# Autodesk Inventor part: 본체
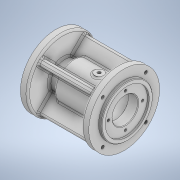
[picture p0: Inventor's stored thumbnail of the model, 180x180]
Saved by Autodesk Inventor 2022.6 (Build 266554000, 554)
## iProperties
Created: 2024-10
Part Number: 본체
Material: 일반
Document SubType Name: Modeling
Designer: Class 001
Density: 1 g/cm^3
Appearance: 기본값
Author: Class 001
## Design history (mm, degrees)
sketch "스케치3"
  geometry: L1 (0, 0)-(15, 0); L2 (15, 0)-(15, 23); L3 (15, 23)-(0, 23); L4 (0, 23)-(0, 0); L5 (15, 0)-(88, 0); L6 (88, 0)-(88, 30); L7 (88, 30)-(15, 30); L8 (15, 30)-(15, 0); 1 further point
  constraints: 16 end point, 4 parallel, 2 horizontal, 2 perpendicular
  dimensions: "d7" = 46 diameter of L3 L1; "d8" = 15 distance of L2.end L3.end; "d9" = 73 distance of L6.end L7.end; "d10" = 60 diameter of L7 L5
revolve "회전1" sketch "스케치3" stored, may be unused: angle "d11" = 90 deg
sketch "스케치4"
  geometry: C1 r 58 at (0, 0); 1 further point
  constraints: 1 centre point, 1 coincident
  dimensions: "d12" = 116 diameter of C1
extrude "돌출1" join sketch "스케치4" distance "d13" = 12; taper "d14" = 0 deg
sketch "스케치5"
  geometry: C1 r 42 at (0, 0); 1 further point
  constraints: 1 centre point, 1 coincident
  dimensions: "d15" = 84 diameter of C1
extrude "돌출2" join sketch "스케치5" distance "d16" = 5; taper "d17" = 0 deg
sketch "스케치6"
  geometry: C1 r 58 at (0, 0); 1 further point
  constraints: 1 centre point, 1 coincident
  dimensions: "d18" = 116 diameter of C1
extrude "돌출3" join sketch "스케치6" distance "d19" = 12; taper "d20" = 0 deg
sketch "스케치7"
  geometry: C1 r 42 at (0, 0); 1 further point
  constraints: 1 centre point, 1 coincident
  dimensions: "d21" = 84 diameter of C1
extrude "돌출4" join sketch "스케치7" distance "d22" = 5; taper "d23" = 0 deg
sketch "스케치8"
  geometry: L1 (105, -42)-(105, 42) reference; L2 (105, 36)-(102, 36); L3 (102, 36)-(102, 0); L4 (102, 0)-(105, 0); L5 (105, 0)-(105, 36); L6 (102, 0)-(86, 0); L7 (86, 0)-(86, 21); L8 (86, 21)-(102, 21); L9 (102, 21)-(102, 0); L10 (86, 0)-(32, 0); L11 (32, 0)-(32, 25); L12 (32, 25)-(86, 25); L13 (86, 25)-(86, 0); L14 (32, 0)-(20, 0); L15 (20, 0)-(20, 21); L16 (20, 21)-(32, 21); L17 (32, 21)-(32, 0); L18 (20, 0)-(2, 0); L19 (2, 0)-(2, 18); L20 (2, 18)-(20, 18); L21 (20, 18)-(20, 0); L22 (2, 0)-(-2, 0); L23 (-2, 0)-(-2, 16); L24 (-2, 16)-(2, 16); L25 (2, 16)-(2, 0); L26 (-2, 0)-(-5, 0); L27 (-5, 0)-(-5, 10.5); L28 (-5, 10.5)-(-2, 10.5); L29 (-2, 10.5)-(-2, 0); 8 further points
  constraints: 56 end point, 14 parallel, 7 horizontal, 7 perpendicular, 1 horizontal alignment, 1 point on line
  dimensions: "d24" = 72 diameter of L2 L4; "d25" = 3 distance of L2.start L2.end; "d26" = 42 diameter of L8 L6; "d27" = 16 distance of L7.end L8.end; "d28" = 54 distance of L11.end L12.end; "d29" = 50 diameter of L12 L10; "d30" = 12 distance of L15.end L16.end; "d31" = 42 diameter of L16 L14; "d32" = 18 distance of L19.end L20.end; "d33" = 36 diameter of L20 L18; "d34" = 4 distance of L23.end L24.end; "d35" = 32 diameter of L24 L22; "d36" = 3 distance of L27.end L28.end; "d37" = 21 diameter of L28 L26
revolve "회전2" stored, may be unused: angle "d38" = 90 deg
revolve "회전3" stored, may be unused: angle "d39" = 90 deg
fillet "모깎기1" dims "d40" = 3
fillet "모깎기2" dims "d41" = 0.6
chamfer "모따기1" distance "d42" = 1; stored, may be unused: second distance "d43" = 2, angle "d44" = 30 deg
fillet "모깎기3" dims "d45" = 0.6
fillet "모깎기4" dims "d46" = 3
chamfer "모따기2" distance "d47" = 1; stored, may be unused: second distance "d48" = 2, angle "d49" = 30 deg
chamfer "모따기3" distance "d50" = 1; stored, may be unused: second distance "d51" = 2, angle "d52" = 30 deg
sketch "스케치9"
  geometry: C1 r 36 at (0, 0); 1 further point
  constraints: 1 centre point, 1 coincident
  dimensions: "d53" = 72 diameter of C1
extrude "돌출5" cut sketch "스케치9" distance "d54" = 4; taper "d55" = 0 deg
fillet "모깎기5" dims "d56" = 3
fillet "모깎기6" dims "d57" = 3
sketch "스케치10"
  geometry: 2 further points
  constraints: 1 horizontal alignment
  dimensions: "d58" = 28 distance of point (0, 0) point (28, 0)
hole "구멍1" sketch "스케치10" at (28, 0) diameter "d59" = 4.134; stored, may be unused: countersink angle "d63" = 82 deg, drill point angle "d65" = 118 deg; dims "d60" = 10, "d61" = 11, "d62" = 2.6, "d64" = 12
node "작업 평면4"
sketch "스케치12"
  geometry: L1 (-105, -41)-(-105, 41) reference; C1 r 7.5 at (-59, 0); 2 further points
  constraints: 1 centre point, 1 horizontal alignment, 1 midpoint
  dimensions: "d74" = 15 diameter of C1; "d75" = 46 distance from line of L1 C1.centre
extrude "돌출6" join sketch "스케치12" stored distance "d76" = 4; taper "d77" = 0 deg
sketch "스케치13"
  geometry: C1 r 7.5 at (0, 0) reference; 2 further points
  constraints: 1 coincident
hole "구멍2" sketch "스케치13" at (0, 0) diameter "d78" = 5.1881; stored, may be unused: countersink angle "d82" = 90 deg, drill point angle "d84" = 118 deg; dims "d79" = 12, "d80" = 4, "d81" = 2, "d83" = 16
fillet "모깎기7" dims "d85" = 3
sketch "스케치14"
  geometry: C1 r 58 at (0, 0) reference; A1 r 50 centre (0, 0) between (35.355, -35.355) and (0, -50); 5 further points
  constraints: 6 point on circle, 2 vertical alignment, 1 centre point, 1 coincident
  dimensions: "d87" = 100 diameter of A1; "d88" = 45 deg dimension on point (0, 0) A1.end A1.start; "d89" = 90 deg dimension on point (0, 0) point (-35.355, -35.355) A1.start; "d90" = 45 deg dimension on point (0, 0) point (35.355, 35.355) point (0, 50); "d91" = 90 deg dimension on point (0, 0) point (-35.355, 35.355) point (35.355, 35.355)
hole "구멍3" sketch "스케치14" at (-35.355, 35.355), (35.355, 35.355), (35.355, -35.355), (-35.355, -35.355) diameter "d92" = 5.1881; stored, may be unused: countersink angle "d96" = 90 deg, drill point angle "d98" = 118 deg; dims "d93" = 12, "d94" = 4, "d95" = 2, "d97" = 14
sketch "스케치15"
  geometry: C1 r 58 at (0, 0) reference; C2 r 22 at (0, 0) reference; A1 r 50 centre (0, 0) between (0, 50) and (0, -50); 5 further points
  constraints: 6 point on circle, 2 vertical alignment, 1 centre point, 1 coincident
  dimensions: "d99" = 100 diameter of A1; "d100" = 45 deg dimension on point (0, 0) A1.end point (-35.355, -35.355); "d101" = 90 deg dimension on point (0, 0) point (35.355, -35.355) point (-35.355, -35.355); "d102" = 45 deg dimension on point (0, 0) A1.start point (-35.355, 35.355); "d103" = 90 deg dimension on point (0, 0) point (35.355, 35.355) point (-35.355, 35.355)
hole "구멍4" sketch "스케치15" at (-35.355, 35.355), (35.355, 35.355), (-35.355, -35.355), (35.355, -35.355) diameter "d104" = 5.1881; stored, may be unused: countersink angle "d108" = 90 deg, drill point angle "d110" = 118 deg; dims "d105" = 12, "d106" = 4, "d107" = 2, "d109" = 14
sketch "스케치28"
  geometry: L1 (0, 0)-(-38.184, 38.184); L2 (0, 0)-(-29.81, 0)
  constraints: 4 end point, 1 horizontal
  dimensions: "d130" = 54 distance of L1.start L1.end; "d131" = 45 deg angle of L1 L2
node "작업 평면9"
sketch "스케치29"
  geometry: L1 (0, 0)-(54, 0) reference; L2 (54, 0)-(54, 88); L3 (55, 88)-(-55, 88) reference; L4 (54, 88)-(0, 88); L5 (54, 0)-(0, 0); 1 further point
  constraints: 6 end point, 1 horizontal, 1 midpoint, 1 point on line, 1 vertical
feature "리브2" sketch "스케치29" dims "d133" = 1, "d134" = 10, "d135" = 0, "d136" = 0, "d137" = 1, "d138" = 1
sketch "스케치30"
  geometry: L1 (105, -42)-(105, 42); L2 (105, 36)-(102, 36); L3 (102, 36)-(102, 0); L4 (102, 0)-(105, 0); L5 (105, 0)-(105, 36); L6 (102, 0)-(86, 0); L7 (86, 0)-(86, 21); L8 (86, 21)-(102, 21); L9 (102, 21)-(102, 0); L10 (86, 0)-(32, 0); L11 (32, 0)-(32, 25); L12 (32, 25)-(86, 25); L13 (86, 25)-(86, 0); L14 (32, 0)-(20, 0); L15 (20, 0)-(20, 21); L16 (20, 21)-(32, 21); L17 (32, 21)-(32, 0); L18 (20, 0)-(2, 0); L19 (2, 0)-(2, 18); L20 (2, 18)-(20, 18); L21 (20, 18)-(20, 0); L22 (2, 0)-(-2, 0); L23 (-2, 0)-(-2, 16); L24 (-2, 16)-(2, 16); L25 (2, 16)-(2, 0); L26 (-2, 0)-(-5, 0); L27 (-5, 0)-(-5, 10.5); L28 (-5, 10.5)-(-2, 10.5); L29 (-2, 10.5)-(-2, 0); 15 further points
  constraints: 58 end point, 14 parallel, 7 horizontal, 7 perpendicular, 1 horizontal alignment, 1 point on line
  dimensions: "d139" = 72 diameter of L2 L4; "d140" = 3 distance of L2.start L2.end; "d141" = 42 diameter of L8 L6; "d142" = 16 distance of L7.end L8.end; "d143" = 54 distance of L11.end L12.end; "d144" = 50 diameter of L12 L10; "d145" = 12 distance of L15.end L16.end; "d146" = 42 diameter of L16 L14; "d147" = 18 distance of L19.end L20.end; "d148" = 36 diameter of L20 L18; "d149" = 4 distance of L23.end L24.end; "d150" = 32 diameter of L24 L22; "d151" = 3 distance of L27.end L28.end; "d152" = 21 diameter of L28 L26
revolve "회전4" sketch "스케치30" stored, may be unused: angle "d153" = 90 deg
fillet "모깎기8" dims "d154" = 3
chamfer "모따기4" distance "d155" = 1; stored, may be unused: second distance "d156" = 2, angle "d157" = 45 deg
fillet "모깎기9" dims "d158" = 0.6
fillet "모깎기10" dims "d159" = 0.6
fillet "모깎기11" dims "d160" = 3
fillet "모깎기12" dims "d164" = 3
fillet "모깎기13" dims "d165" = 3
fillet "모깎기14" dims "d166" = 3
fillet "모깎기15" dims "d167" = 3
node "솔리드1"
pattern_circular "원형 패턴1" dims angle "d67" = 360 deg
mirror "미러1"
pattern_circular "원형 패턴2" dims angle "d162" = 360 deg
feature "A9D066F2-1C7D-4E18-AEED-F7BC21143FA4" dims "d92" = 5.1881, "d93" = 12, "d94" = 4, "d95" = 2, "d96" = 90 deg, "d97" = 14, "d98" = 118 deg
other parameters: "d73" = 32, "d132" = 90 deg
